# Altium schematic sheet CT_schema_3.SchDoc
size 493 x 398 mm
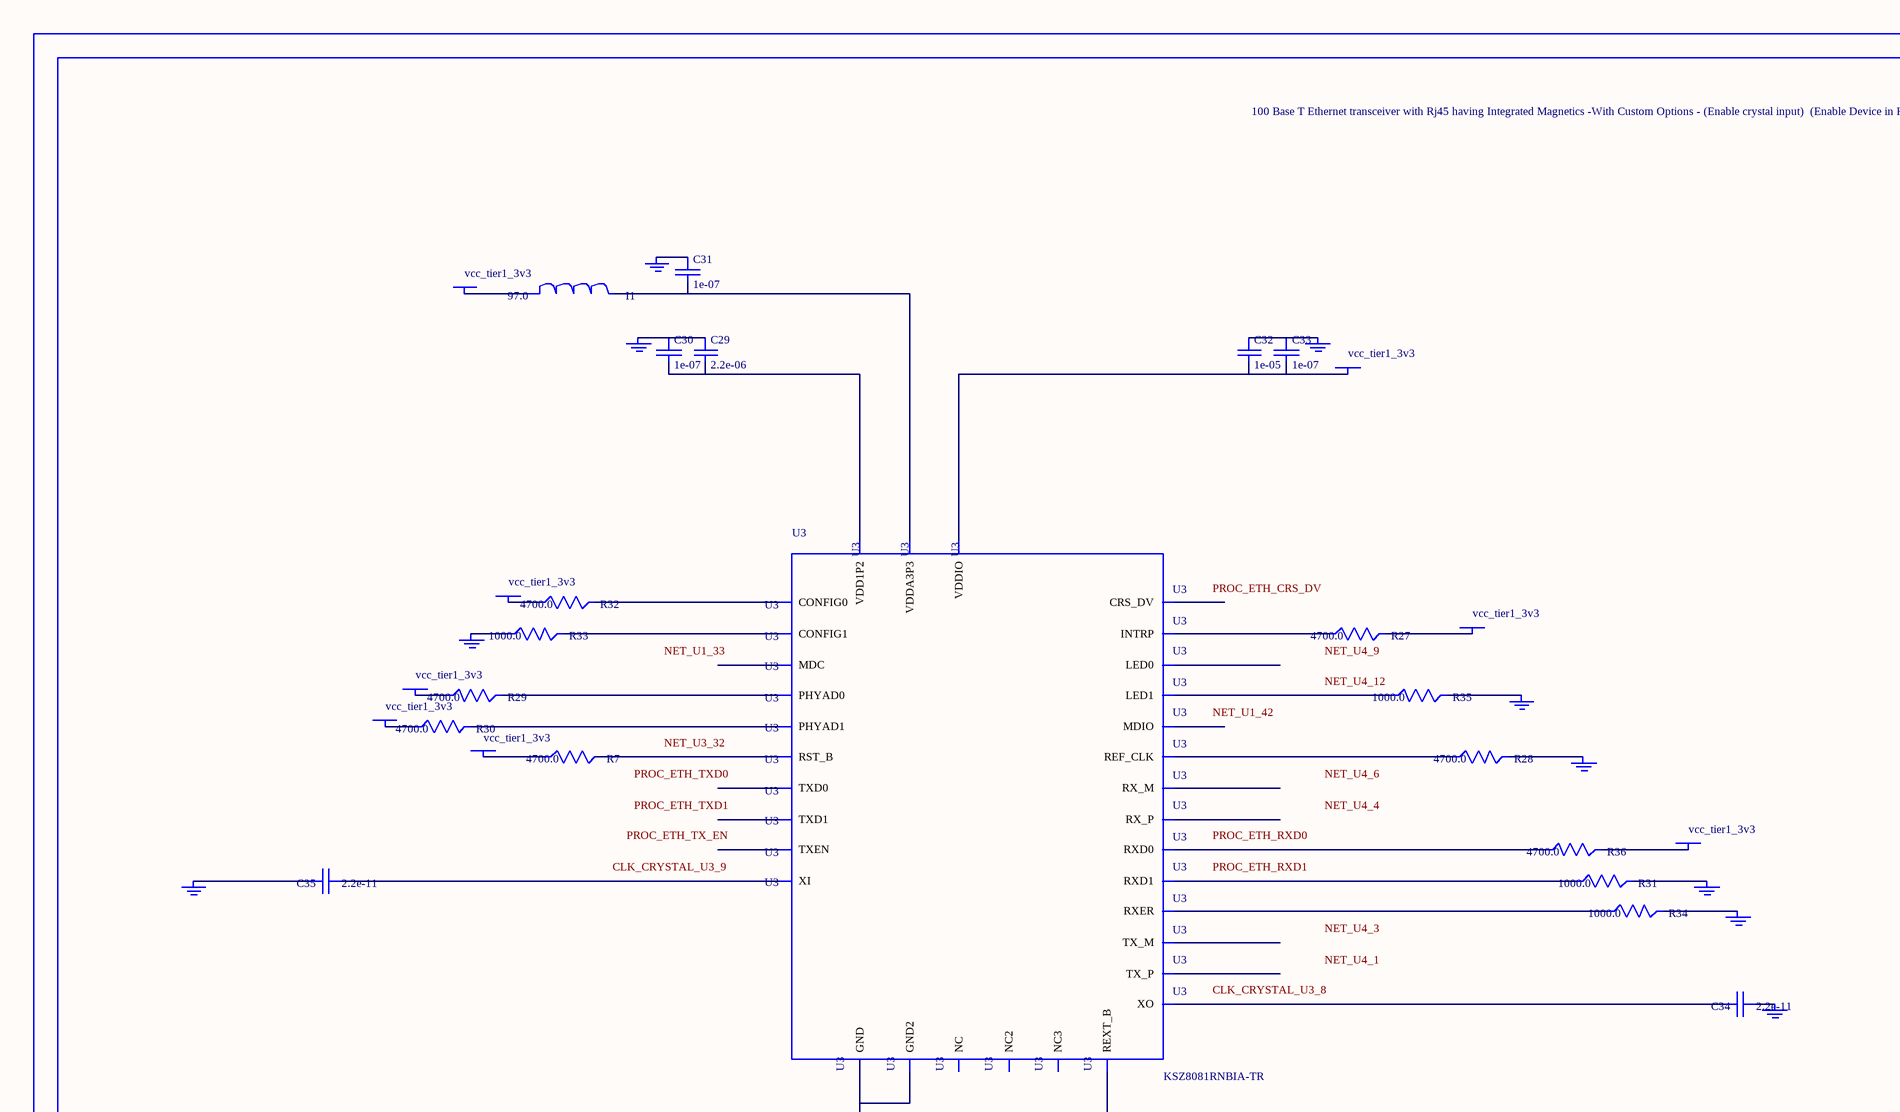
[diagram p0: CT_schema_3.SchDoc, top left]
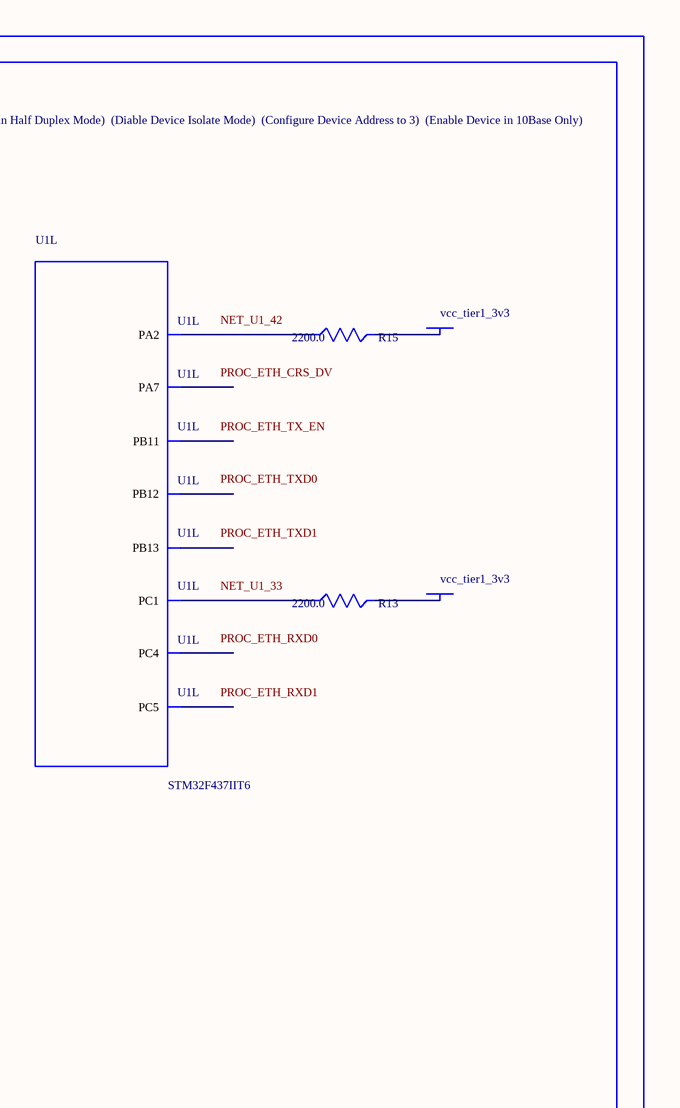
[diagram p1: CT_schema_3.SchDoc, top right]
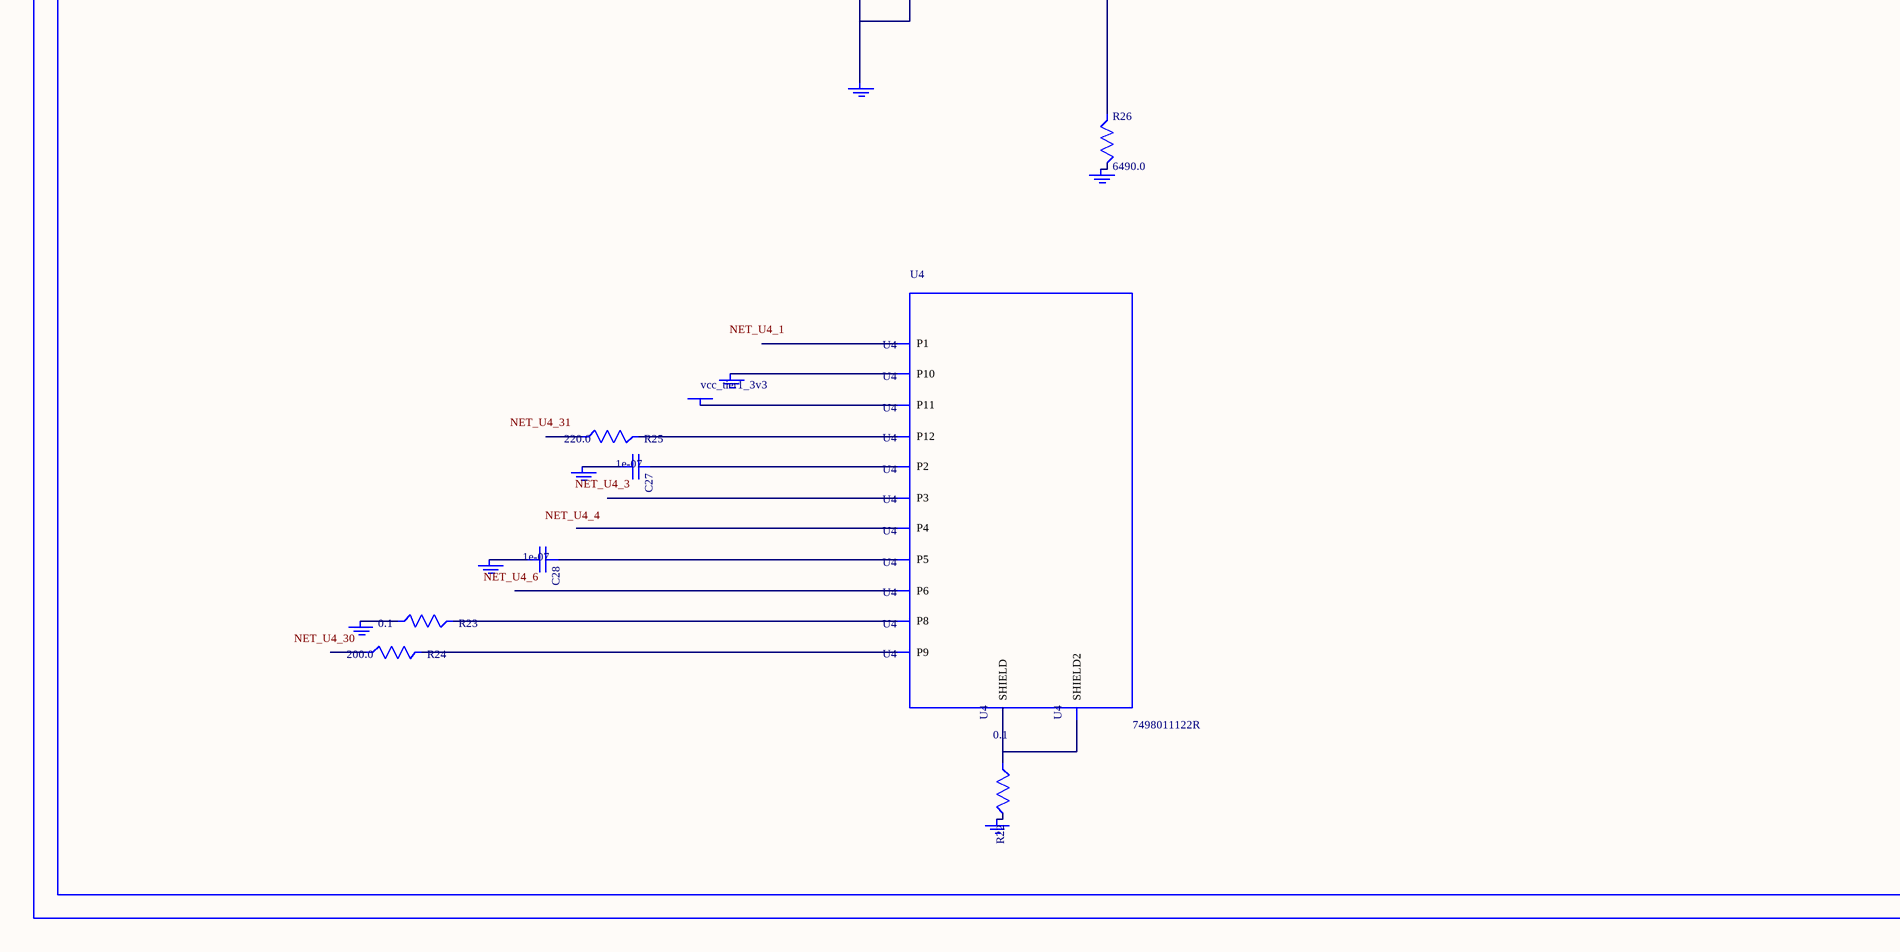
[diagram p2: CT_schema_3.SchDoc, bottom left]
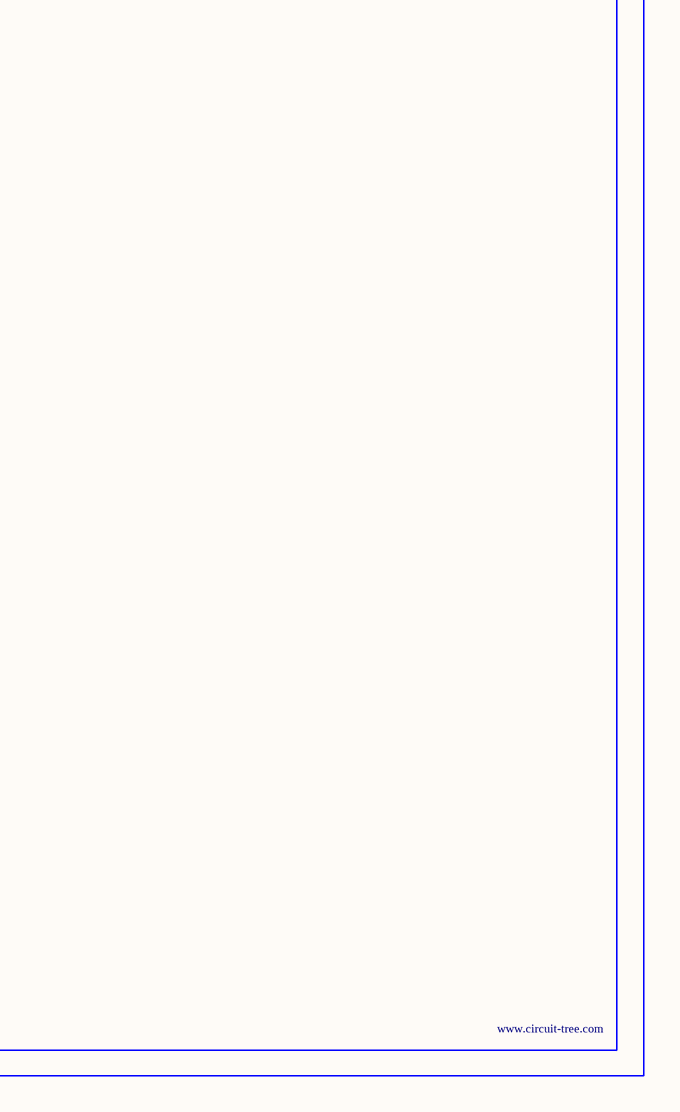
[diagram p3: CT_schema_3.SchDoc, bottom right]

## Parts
BORDER2  (no value)
C27  1e-07  [C0402]
C28  1e-07  [C0402]
C29  2.2e-06  [C0603]
C30  1e-07  [C0402]
C31  1e-07  [C0402]
C32  1e-05  [C0805]
C33  1e-07  [C0402]
C34  2.2e-11  [C0402]
C35  2.2e-11  [C0402]
GND_INSTANCE_2_0  (no value)
GND_INSTANCE_2_1  (no value)
GND_INSTANCE_2_2  (no value)
GND_INSTANCE_2_3  (no value)
GND_INSTANCE_2_4  (no value)
GND_INSTANCE_2_5  (no value)
GND_INSTANCE_2_6  (no value)
GND_INSTANCE_2_7  (no value)
GND_INSTANCE_2_8  (no value)
GND_INSTANCE_2_9  (no value)
GND_INSTANCE_2_10  (no value)
GND_INSTANCE_2_11  (no value)
GND_INSTANCE_2_12  (no value)
GND_INSTANCE_2_13  (no value)
GND_INSTANCE_2_14  (no value)
GND_INSTANCE_2_15  (no value)
GND_INSTANCE_2_16  (no value)
I1  97.0  [R0603]
POWER_INSTANCE_2_0  vcc_tier1_3v3
POWER_INSTANCE_2_1  vcc_tier1_3v3
POWER_INSTANCE_2_2  vcc_tier1_3v3
POWER_INSTANCE_2_3  vcc_tier1_3v3
POWER_INSTANCE_2_4  vcc_tier1_3v3
POWER_INSTANCE_2_5  vcc_tier1_3v3
POWER_INSTANCE_2_6  vcc_tier1_3v3
POWER_INSTANCE_2_7  vcc_tier1_3v3
POWER_INSTANCE_2_8  vcc_tier1_3v3
POWER_INSTANCE_2_9  vcc_tier1_3v3
POWER_INSTANCE_2_10  vcc_tier1_3v3
R7  4700.0  [R0603]
R13  2200.0  [R0603]
R15  2200.0  [R0603]
R22  0.1  [R0603]
R23  0.1  [R0603]
R24  200.0  [R0603]
R25  220.0  [R0603]
R26  6490.0  [R0603]
R27  4700.0  [R0603]
R28  4700.0  [R0603]
R29  4700.0  [R0603]
R30  4700.0  [R0603]
R31  1000.0  [R0603]
R32  4700.0  [R0603]
R33  1000.0  [R0603]
R34  1000.0  [R0603]
R35  1000.0  [R0603]
R36  4700.0  [R0603]
U1  STM32F437IIT6  [LQFP176]  (part L of 16)
U3  KSZ8081RNBIA-TR  [QFN-32]
U4  7498011122R  [7498011122R]

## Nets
NetC27_1: C27.1 U4.2(P2)
NetC27_2: C27.2 GND_INSTANCE_2_12.0(GND)
NetC28_1: C28.1 U4.5(P5)
NetC28_2: C28.2 GND_INSTANCE_2_13.0(GND)
NetC29_1: C29.1 C30.1 GND_INSTANCE_2_0.0(GND)
NetC29_2: C29.2 C30.2 U3.2(VDD1P2)
NetC31_1: C31.1 GND_INSTANCE_2_1.0(GND)
NetC31_2: C31.2 I1.2 U3.3(VDDA3P3)
NetC32_1: C32.1 C33.1 GND_INSTANCE_2_6.0(GND)
NetC32_2: C32.2 C33.2 POWER_INSTANCE_2_4.0(PWR) U3.17(VDDIO)
NetC34_1: C34.1 GND_INSTANCE_2_2.0(GND)
NetC34_2: C34.2 U3.8(XO)
NetC35_1: C35.1 U3.9(XI)
NetC35_2: C35.2 GND_INSTANCE_2_3.0(GND)
NetGND_INSTANCE_2_4_0: GND_INSTANCE_2_4.0(GND) R26.2
NetGND_INSTANCE_2_5_0: GND_INSTANCE_2_5.0(GND) R31.2
NetGND_INSTANCE_2_7_0: GND_INSTANCE_2_7.0(GND) R28.2
NetGND_INSTANCE_2_8_0: GND_INSTANCE_2_8.0(GND) R34.2
NetGND_INSTANCE_2_9_0: GND_INSTANCE_2_9.0(GND) R33.1
NetGND_INSTANCE_2_10_0: GND_INSTANCE_2_10.0(GND) R35.2
NetGND_INSTANCE_2_11_0: GND_INSTANCE_2_11.0(GND) U3.1(GND) U3.EXP(GND2)
NetGND_INSTANCE_2_14_0: GND_INSTANCE_2_14.0(GND) R23.1
NetGND_INSTANCE_2_15_0: GND_INSTANCE_2_15.0(GND) U4.10(P10)
NetGND_INSTANCE_2_16_0: GND_INSTANCE_2_16.0(GND) R22.2
NetI1_1: I1.1 POWER_INSTANCE_2_0.0(PWR)
NetPOWER_INSTANCE_2_1_0: POWER_INSTANCE_2_1.0(PWR) R29.1
NetPOWER_INSTANCE_2_2_0: POWER_INSTANCE_2_2.0(PWR) R30.1
NetPOWER_INSTANCE_2_3_0: POWER_INSTANCE_2_3.0(PWR) R36.2
NetPOWER_INSTANCE_2_5_0: POWER_INSTANCE_2_5.0(PWR) R27.2
NetPOWER_INSTANCE_2_6_0: POWER_INSTANCE_2_6.0(PWR) R32.1
NetPOWER_INSTANCE_2_7_0: POWER_INSTANCE_2_7.0(PWR) R7.1
NetPOWER_INSTANCE_2_8_0: POWER_INSTANCE_2_8.0(PWR) R13.2
NetPOWER_INSTANCE_2_9_0: POWER_INSTANCE_2_9.0(PWR) R15.2
NetPOWER_INSTANCE_2_10_0: POWER_INSTANCE_2_10.0(PWR) U4.11(P11)
NetR7_2: R7.2 U3.32(RST_B)
NetR13_1: R13.1 U1.33(PC1)
NetR15_1: R15.1 U1.42(PA2)
NetR22_1: R22.1 U4.13(SHIELD) U4.14(SHIELD2)
NetR23_2: R23.2 U4.8(P8)
NetR24_2: R24.2 U4.9(P9)
NetR25_2: R25.2 U4.12(P12)
NetR26_1: R26.1 U3.10(REXT_B)
NetR27_1: R27.1 U3.21(INTRP)
NetR28_1: R28.1 U3.19(REF_CLK)
NetR29_2: R29.2 U3.13(PHYAD0)
NetR30_2: R30.2 U3.14(PHYAD1)
NetR31_1: R31.1 U3.15(RXD1)
NetR32_2: R32.2 U3.28(CONFIG0)
NetR33_2: R33.2 U3.29(CONFIG1)
NetR34_1: R34.1 U3.20(RXER)
NetR35_1: R35.1 U3.31(LED1)
NetR36_1: R36.1 U3.16(RXD0)

Not connected (* = marked no-connect by the designer): R24 1; R25 1; U1 53(PA7) 54(PC4) 55(PC5) 80(PB11) 92(PB12) 93(PB13); U3 4(RX_M) 5(RX_P) 6(TX_M) 7(TX_P) 11(MDIO) 12(MDC) 18(CRS_DV) 22(NC) 23(TXEN) 24(TXD0) 25(TXD1) 26(NC2) 27(NC3) 30(LED0); U4 1(P1) 3(P3) 4(P4) 6(P6)

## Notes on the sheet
- Labels drawn without touching a wire or pin: CLK_CRYSTAL_U3_8, CLK_CRYSTAL_U3_9, NET_U1_33, NET_U1_42, NET_U3_32, NET_U4_1, NET_U4_3, NET_U4_4, NET_U4_6, NET_U4_9, NET_U4_12, NET_U4_30, NET_U4_31, PROC_ETH_CRS_DV, PROC_ETH_RXD0, PROC_ETH_RXD1, PROC_ETH_TX_EN, PROC_ETH_TXD0, PROC_ETH_TXD1

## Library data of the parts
BORDER2 = BORDER_PAGE2
C27 C28 C30 C31 C33 = C0402C104K3RACTU
C29 = C0603C225K8RACTU
C32 = C0805C106K8RACTU
C34 C35 = C0402C220K3RAC
GND_INSTANCE_2_0-GND_INSTANCE_2_16 = GND
I1 = I1
POWER_INSTANCE_2_0-POWER_INSTANCE_2_10 = PWR
R7 R27-R30 R32 R36 = RC0603JR-074K7L
R13 R15 = RC0603JR-072K2L
R22 R23 = ERJ-3RSFR10V
R24 = RC0603JR-07200RL
R25 = RC0603JR-07220RL
R26 = ERJ-3EKF6491V
R31 R33-R35 = RC0603JR-071KL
